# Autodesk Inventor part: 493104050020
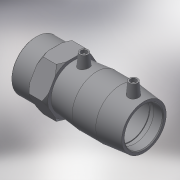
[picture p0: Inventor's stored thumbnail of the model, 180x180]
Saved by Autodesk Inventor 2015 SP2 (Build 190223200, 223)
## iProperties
Created: 2017-06
Part Number: 493104050020
Material: Generic
Description: PLASSON FEMALE TRANSITION COUPLER 50-2"
Document SubType Name: Modeling
Designer: KIM
Mass: 222.107 g
Surface Area: 545.477 cm^2
Volume: 222.107 cm^3
Density: 1 g/cm^3
Appearance: Default
Author: KIM
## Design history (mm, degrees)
derived "493104.ipt"
feature "Solid1::493104.ipt"
tag "TaggingFeature1"
body "Solid1"
other parameters: "d0" = 101, "d2" = 67, "d3" = 49, "d4" = 33.66667, "d5" = 60.3, "d6" = 47.5, "d8" = 168 deg, "d10" = 19.6, "d11" = 6.53333, "d29" = 51, "d30" = 14, "d31" = 35.35, "d34" = 5 deg, "d41" = 4, "d42" = 14, "d43" = 0, "d48" = 3, "d49" = 0, "d57" = 38, "d59" = 56.656, "d60" = 27, "d70" = 67, "d71" = 15, "d72" = 0, "d73" = 45 deg, "d74" = 3.8, "d75" = 45 deg, "d77" = 0.75, "d80" = 1, "L_" = 131, "L_1" = 49, "D_1" = 67, "A_" = 51, "d_2" = 12, "D_" = 38, "R_p" = 56.656
